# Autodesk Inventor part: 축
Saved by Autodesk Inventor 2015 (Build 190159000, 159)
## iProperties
Created: 2026-07
Part Number: 축
Material: 일반
Document SubType Name: Modeling
Designer: USER
Density: 1 g/cm^3
Appearance: 기본값
Author: USER
Author: jhkim
Creation Date: 2026-07-01
Sending System: Autodesk Inventor 2027
Preprocessor: ST-DEVELOPER v20.1
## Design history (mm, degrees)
node "축1"
node "솔리드1"
node "기준1"
